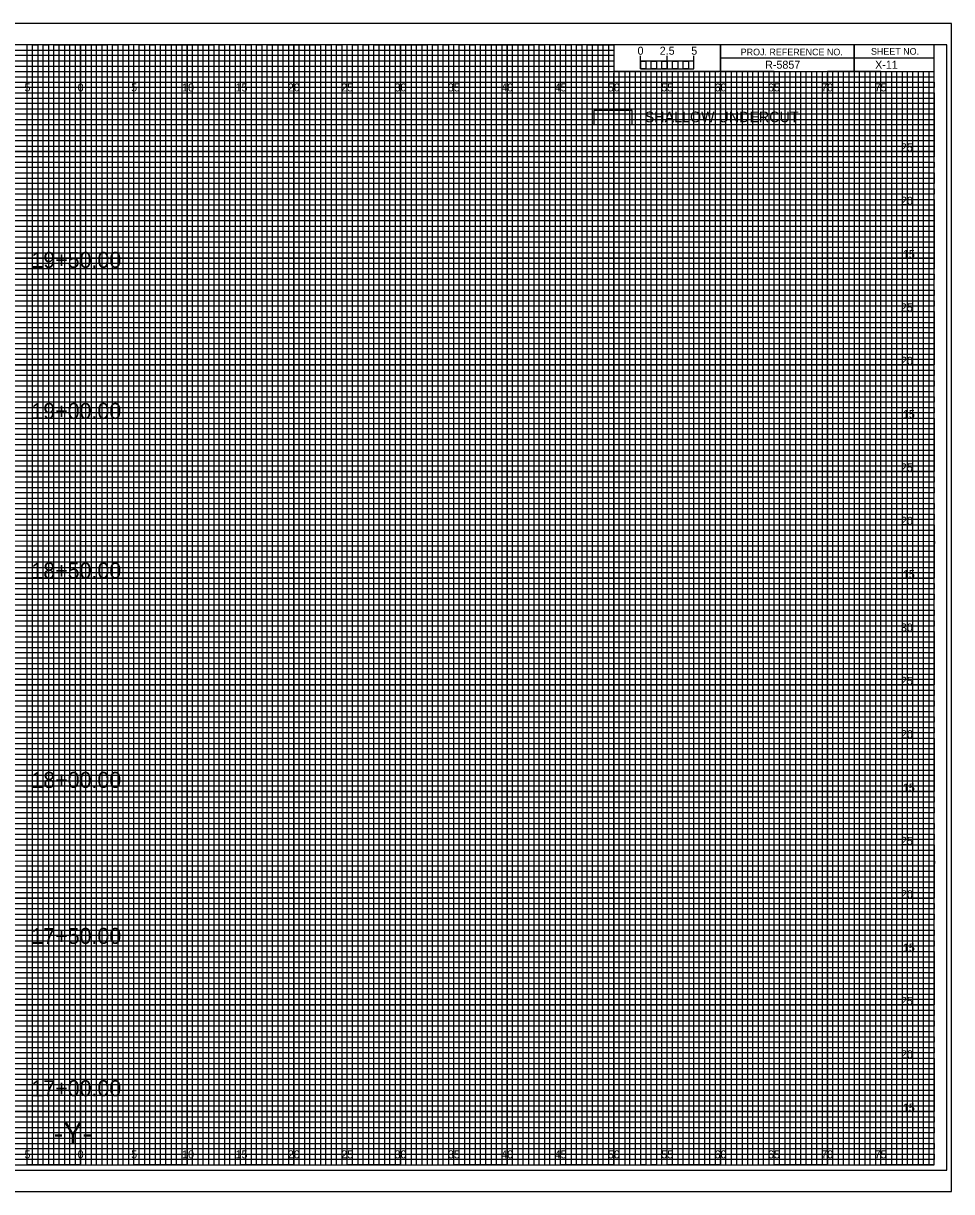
# Model space of a CAD drawing. Extents: x -7 to 162, y -3 to 107.
# Drawn here: x 74.6 to 161.7, y -2.5 to 107 of the extents above; entities that cross this region are included whole.
import ezdxf

# ---------------------------------------------------------------- set-up
doc = ezdxf.new("R2010")
doc.units = 0
for name, color, linetype in [('Old_Level_1', 7, 'Continuous'), ('Prop XS Alignment Label', 7, 'Continuous'), ('Prop XS Bar Scale Labels', 7, 'Continuous'), ('Prop XS Earthwork Undercut', 7, 'Continuous'), ('Prop XS Elevation Labels', 7, 'Continuous'), ('Prop XS Offset Labels', 7, 'Continuous'), ('Prop XS Project Number', 7, 'Continuous'), ('Prop XS Sheet Number', 7, 'Continuous'), ('Prop XS Station Labels', 7, 'Continuous'), ('Sheet Cross Section CELL', 7, 'Continuous'), ('Sheet Cross Section Grid Major CELL', 7, 'Continuous'), ('Sheet Cross Section Grid Middle CELL', 7, 'Continuous'), ('Sheet Cross Section Grid Minor 1 CELL', 7, 'Continuous'), ('Sheet Cross Section Grid Minor 2 CELL', 7, 'Continuous'), ('Sheet Cross Section Scale CELL', 7, 'Continuous'), ('Sheet Cutting Line CELL', 7, 'Continuous'), ('Sheet DOT Grid CELL', 7, 'Continuous'), ('Sheet Plot Border Inside CELL', 7, 'Continuous'), ('Sheet Plot Border Outside CELL', 7, 'Continuous')]:
    doc.layers.add(name, color=color, linetype=linetype)

msp = doc.modelspace()

# ---------------------------------------------------------------- linework, layer by layer
at = {"layer": 'Prop XS Earthwork Undercut'}
msp.add_lwpolyline([(128.12, 97.52), (131.7, 97.52), (131.7, 98.83), (128.12, 98.83), (128.12, 97.52)], dxfattribs=at)
at = {"layer": 'Sheet Cross Section CELL'}
for p, q in [((152.5, 105), (152.5, 102.5)), ((152.5, 102.5), (152.5, 105)), ((160, 103.75), (140, 103.75)), ((140, 103.75), (140, 102.5)), ((140, 102.5), (160, 102.5))]:
    msp.add_line(p, q, dxfattribs=at)
for points in [[(160, 105), (0, 105), (0, 0), (160, 0)], [(140, 105), (130, 105), (130, 102.52), (140, 102.52)], [(160, 105), (140, 105), (140, 102.5), (160, 102.5)]]:
    msp.add_lwpolyline(points, close=True, dxfattribs=at)
at = {"layer": 'Sheet Cross Section Grid Major CELL'}
for p, q in [((75, 105), (70, 105)), ((75, 0), (75, 105)), ((85, 105), (80, 105)), ((80, 105), (80, 0)), ((85, 0), (85, 105)), ((95, 105), (90, 105)), ((90, 105), (90, 0)), ((95, 0), (95, 105)), ((105, 105), (100, 105)), ((100, 105), (100, 0)), ((105, 0), (105, 105)), ((115, 105), (110, 105)), ((110, 105), (110, 0)), ((115, 0), (115, 105)), ((125, 105), (120, 105)), ((120, 105), (120, 0)), ((125, 0), (125, 105)), ((130, 105), (130, 0)), ((135, 0), (135, 102.5)), ((145, 102.5), (140, 102.5)), ((140, 102.5), (140, 0)), ((145, 0), (145, 102.5)), ((155, 102.5), (150, 102.5)), ((150, 102.5), (150, 0)), ((155, 0), (155, 102.5)), ((80, 0), (75, 0)), ((90, 0), (85, 0)), ((100, 0), (95, 0)), ((110, 0), (105, 0)), ((120, 0), (115, 0)), ((130, 0), (125, 0)), ((140, 0), (135, 0)), ((150, 0), (145, 0)), ((160, 0), (155, 0)), ((160, 0), (160, 0))]:
    msp.add_line(p, q, dxfattribs=at)
for points in [[(0, 100), (160, 100), (160, 95), (0, 95)], [(0, 90), (160, 90), (160, 85), (0, 85)], [(0, 80), (160, 80), (160, 75), (0, 75)], [(0, 70), (160, 70), (160, 65), (0, 65)], [(0, 60), (160, 60), (160, 55), (0, 55)], [(0, 50), (160, 50), (160, 45), (0, 45)], [(0, 40), (160, 40), (160, 35), (0, 35)], [(0, 30), (160, 30), (160, 25), (0, 25)], [(0, 20), (160, 20), (160, 15), (0, 15)], [(0, 10), (160, 10), (160, 5), (0, 5)]]:
    msp.add_lwpolyline(points, dxfattribs=at)
at = {"layer": 'Sheet Cross Section Grid Middle CELL'}
for points in [[(72.5, 0), (77.5, 0), (77.5, 105), (82.5, 105), (82.5, 0), (87.5, 0), (87.5, 105), (92.5, 105), (92.5, 0), (97.5, 0), (97.5, 105), (102.5, 105), (102.5, 0), (107.5, 0), (107.5, 105), (112.5, 105), (112.5, 0), (117.5, 0), (117.5, 105), (122.5, 105), (122.5, 0), (127.5, 0), (127.5, 105), (129.97, 105), (130, 105), (130, 102.5), (132.5, 102.5), (132.5, 0), (137.5, 0), (137.5, 102.5), (142.5, 102.5), (142.5, 0), (147.5, 0), (147.5, 102.5), (152.5, 102.5), (152.5, 0), (157.5, 0), (157.5, 102.5)], [(0, 102.5), (137.5, 102.5)], [(0, 92.5), (160, 92.5), (160, 97.5), (0, 97.5)], [(0, 82.5), (160, 82.5), (160, 87.5), (0, 87.5)], [(0, 72.5), (160, 72.5), (160, 77.5), (0, 77.5)], [(0, 62.5), (160, 62.5), (160, 67.5), (0, 67.5)], [(0, 52.5), (160, 52.5), (160, 57.5), (0, 57.5)], [(0, 42.5), (160, 42.5), (160, 47.5), (0, 47.5)], [(0, 32.5), (160, 32.5), (160, 37.5), (0, 37.5)], [(0, 22.5), (160, 22.5), (160, 27.5), (0, 27.5)], [(0, 12.5), (160, 12.5), (160, 17.5), (0, 17.5)], [(0, 2.5), (160, 2.5), (160, 7.5), (0, 7.5)]]:
    msp.add_lwpolyline(points, dxfattribs=at)
at = {"layer": 'Sheet Cross Section Grid Minor 1 CELL'}
for p, q in [((0, 104.5), (130, 104.5)), ((130, 104.5), (130, 103.99)), ((130, 103.99), (0, 103.99)), ((0, 103.5), (130, 103.5)), ((130, 102.95), (0, 102.95)), ((130, 103.5), (130, 102.95)), ((0, 102), (160, 102))]:
    msp.add_line(p, q, dxfattribs=at)
for points in [[(0, 101.5), (135, 101.5), (160, 101.5), (160, 101), (0, 101)], [(0, 100.5), (160, 100.5), (160, 99.5), (0, 99.5)], [(0, 99), (160, 99), (160, 98.5), (0, 98.49)], [(0, 98), (160, 98), (160, 97), (0, 97)], [(0, 96.5), (160, 96.5), (160, 96), (0, 96)], [(0, 95.5), (160, 95.5), (160, 94.5), (0, 94.5)], [(0, 94), (160, 94), (160, 93.5), (0, 93.5)], [(0, 93), (160, 93), (160, 92), (0, 92)], [(0, 91.5), (160, 91.5), (160, 91), (0, 91)], [(0, 90.5), (160, 90.5), (160, 89.5), (0, 89.5)], [(0, 89), (160, 89), (160, 88.5), (0, 88.5)], [(0, 88), (160, 88), (160, 86.98), (160, 86.5), (160, 86), (0, 86)], [(0, 87), (160, 87), (160, 86.5), (0, 86.5)], [(0, 85.5), (160, 85.5), (160, 84.5), (0, 84.52)], [(0, 84.52), (160, 84.5), (160, 84), (0, 84)], [(0, 83.5), (160, 83.5), (160, 83), (0, 83)], [(0, 82), (160, 82), (160, 81.5), (0, 81.5)], [(0, 81), (160, 81), (160, 80.5), (0, 80.5)], [(-0.04, 79.45), (160, 79.45), (160, 78.94), (-0.04, 78.94)], [(0, 78.5), (160, 78.5), (160, 78), (0, 78)], [(0, 77), (160, 77), (160, 76.5), (0, 76.5)], [(0, 76), (160, 76), (160, 75.5), (0, 75.5)], [(0, 74.5), (160, 74.5), (160, 74), (0, 74)], [(0, 73.5), (160, 73.5), (160, 73), (0, 73)], [(0, 72), (160, 72), (160, 71.5), (0, 71.5)], [(0, 71), (160, 71), (160, 70.5), (0, 70.5)], [(0, 69.5), (160, 69.5), (160, 68.99), (0, 69)], [(0, 68.5), (160, 68.5), (160, 68), (0, 68)], [(0, 67), (160, 67), (160, 66.5), (0, 66.5)], [(0, 66), (160, 66), (160, 65.5), (0, 65.5)], [(0, 64.5), (160, 64.5), (160, 64), (0, 64)], [(0, 63.5), (160, 63.5), (160, 63), (0, 63)], [(0, 62), (160, 62), (160, 61.5), (0, 61.5)], [(0, 61), (160, 61), (160, 60.5), (0, 60.5)], [(0, 59.5), (160, 59.5), (160, 59), (0, 59)], [(0, 58.5), (160.03, 58.45), (160, 58), (0, 58)], [(0, 57), (160, 57), (160, 56.5), (0, 56.5)], [(0, 56), (160, 56), (160, 55.5), (0, 55.5)], [(0, 54.5), (160, 54.5), (160, 54), (0, 54)], [(0, 53.5), (160, 53.5), (160, 53), (0, 53)], [(0, 52), (160, 52), (160, 51.5), (0, 51.5)], [(0, 51), (160, 51), (160, 50.5), (0, 50.5)], [(0, 49.5), (160, 49.5), (160, 49), (0, 49)], [(0, 48.5), (160, 48.5), (160, 48), (0, 48)], [(0, 47), (160, 47), (160, 46.5), (0, 46.5)], [(0, 46), (160, 46), (160, 45.5), (0, 45.5)], [(0, 44.5), (160, 44.5), (160, 44), (0, 44)], [(0, 43.5), (160, 43.5), (160, 43), (0, 43)], [(0, 42), (160, 42), (160, 41.5), (0, 41.5)], [(0, 41), (160, 41), (160, 40.5), (0, 40.5)], [(0, 39.5), (160, 39.5), (160, 38.99), (0, 39)], [(0, 38.5), (160, 38.5), (160, 38), (0, 38)], [(0, 37), (160, 37), (160, 36.5), (0, 36.5)], [(0, 36), (160, 36), (160, 35.5), (0, 35.5)], [(0, 34.5), (160, 34.5), (160, 34), (0, 34)], [(0, 33.5), (160, 33.5), (160, 33), (0, 33)], [(0, 32), (160, 32), (160, 31.5), (0, 31.5)], [(0, 31), (160, 31), (160, 30.5), (0, 30.5)], [(0, 29.5), (160, 29.5), (160, 29), (0, 29)], [(0, 28.5), (160.03, 28.46), (160, 28), (0, 28)], [(0, 27), (160, 27), (160, 26.5), (0, 26.5)], [(0, 26), (160, 26), (160, 25.5), (0, 25.5)], [(0, 24.5), (160, 24.5), (160, 24), (0, 24)], [(0, 23.5), (160, 23.5), (160, 23), (0, 23)], [(0, 22), (160, 22), (160, 21.5), (0, 21.5)], [(0, 21), (160, 21), (160, 20.5), (0, 20.5)], [(0, 19.5), (160, 19.5), (160, 19), (0, 19)], [(0, 18.5), (160, 18.5), (160, 18), (0, 18)], [(0, 17), (160, 17), (160, 16.5), (0, 16.5)], [(0, 16), (160, 16), (160, 15.5), (0, 15.5)], [(0, 14.5), (160, 14.5), (160, 14), (0, 14)], [(0, 13.5), (160, 13.5), (160, 13), (0, 13)], [(0, 12), (160, 12), (160, 11.5), (0, 11.5)], [(0, 11), (160, 11), (160, 10.5), (0, 10.5)], [(0, 9.5), (160, 9.5), (160, 9), (0, 9)], [(0, 8.5), (160, 8.5), (160, 8), (0, 8)], [(0, 7), (160, 7), (160, 6.5), (0, 6.5)], [(0, 6), (160, 6), (160, 5.5), (0, 5.5)], [(0, 4.5), (160, 4.5), (160, 4), (0, 4)], [(0, 3.5), (160, 3.5), (160, 3), (0, 3)], [(0, 2), (160, 2), (160, 1.5), (0, 1.5)], [(0, 1), (160, 1), (160, 0.5), (0, 0.5)]]:
    msp.add_lwpolyline(points, dxfattribs=at)
at = {"layer": 'Sheet Cross Section Grid Minor 2 CELL'}
for p, q in [((133.5, 102.5), (133, 102.5)), ((133, 102.5), (133, 0)), ((133.5, 0), (133.5, 102.5)), ((134.5, 102.5), (134, 102.5)), ((134, 102.5), (134, 0)), ((134.5, 0), (134.5, 102.5)), ((133, 0), (132.5, 0)), ((134, 0), (133.5, 0))]:
    msp.add_line(p, q, dxfattribs=at)
for points in [[(75, 0), (75.5, 0), (75.5, 105), (76, 105), (76, 0)], [(76, 0), (76.5, 0), (76.5, 105), (77, 105), (77, 0)], [(77.5, 0), (78, 0), (78, 105), (78.5, 105), (78.5, 0)], [(78.5, 0), (79, 0), (79, 105), (79.5, 105), (79.5, 0)], [(80, 0), (80.5, 0), (80.5, 105), (81, 105), (81, 0)], [(81, 0), (81.5, 0), (81.5, 105), (82, 105), (82, 0)], [(82.5, 0), (83, 0), (83, 105), (83.5, 105), (83.5, 0)], [(83.5, 0), (84, 0), (84, 105), (84.5, 105), (84.5, 0)], [(85, 0), (85.5, 0), (85.5, 105), (86, 105), (86, 0)], [(86, 0), (86.5, 0), (86.5, 105), (87, 105), (87, 0)], [(87.5, 0), (88, 0), (88, 105), (88.5, 105), (88.5, 0)], [(88.5, 0), (89, 0), (89, 105), (89.5, 105), (89.5, 0)], [(90, 0), (90.5, 0), (90.5, 105), (91, 105), (91, 0)], [(91, 0), (91.5, 0), (91.5, 105), (92, 105), (92, 0)], [(92.5, 0), (93, 0), (93, 105), (93.5, 105), (93.5, 0)], [(93.5, 0), (94, 0), (94, 105), (94.5, 105), (94.5, 0)], [(95, 0), (95.5, 0), (95.5, 105), (96, 105), (96, 0)], [(96, 0), (96.5, 0), (96.5, 105), (97, 105), (97, 0)], [(97.5, 0), (98, 0), (98, 105), (98.5, 105), (98.5, 0)], [(98.5, 0), (99, 0), (99, 105), (99.5, 105), (99.5, 0)], [(100, 0), (100.5, 0), (100.5, 105), (101, 105), (101, 0)], [(101, 0), (101.5, 0), (101.5, 105), (102, 105), (102, 0)], [(102.5, 0), (103, 0), (103, 105), (103.5, 105), (103.5, 0)], [(103.5, 0), (104, 0), (104, 105), (104.5, 105), (104.5, 0)], [(105, 0), (105.5, 0), (105.5, 105), (106, 105), (106, 0)], [(106, 0), (106.5, 0), (106.5, 105), (107, 105), (107, 0)], [(107.5, 0), (108, 0), (108, 105), (108.5, 105), (108.5, 0)], [(108.5, 0), (109, 0), (109, 105), (109.5, 105), (109.5, 0)], [(110, 0), (110.5, 0), (110.5, 105), (111, 105), (111, 0)], [(111, 0), (111.5, 0), (111.5, 105), (112, 105), (112, 0)], [(112.5, 0), (113, 0), (113, 105), (113.5, 105), (113.5, 0)], [(113.5, 0), (114, 0), (114, 105), (114.5, 105), (114.5, 0)], [(115, 0), (115.5, 0), (115.5, 105), (116, 105), (116, 0)], [(116, 0), (116.5, 0), (116.5, 105), (117, 105), (117, 0)], [(117.5, 0), (118, 0), (118, 105), (118.5, 105), (118.5, 0)], [(118.5, 0), (119, 0), (119, 105), (119.5, 105), (119.5, 0)], [(120, 0), (120.5, 0), (120.5, 105), (121, 105), (121, 0)], [(121, 0), (121.5, 0), (121.5, 105), (122, 105), (122, 0)], [(122.5, 0), (123, 0), (123, 105), (123.5, 105), (123.5, 0)], [(123.5, 0), (124, 0), (124, 105), (124.5, 105), (124.5, 0)], [(125, 0), (125.5, 0), (125.5, 105), (126, 105), (126, 0)], [(126, 0), (126.5, 0), (126.5, 105), (127, 105), (127, 0)], [(127.5, 0), (128, 0), (128, 105), (128.5, 105), (128.5, 0)], [(128.5, 0), (129, 0), (129, 105), (129.5, 105), (129.5, 0)], [(130, 0), (130.5, 0), (130.5, 102.5), (131.01, 102.5), (131.01, 0)], [(131, 0), (131.5, 0), (131.5, 102.5), (132, 102.5), (132, 0)], [(135, 0), (135.49, 0), (135.49, 102.5), (136, 102.5), (136, 0)], [(136, 0), (136.5, 0), (136.5, 102.5), (137.03, 102.5), (137.03, 0)], [(137.5, 0), (138, 0), (138, 102.5), (138.5, 102.5), (138.5, 0)], [(138.5, 0), (139, 0), (139, 102.5), (139.5, 102.5), (139.5, 0)], [(140, 0), (140.5, 0), (140.5, 102.5), (141, 102.5), (141, 0)], [(141, 0), (141.5, 0), (141.5, 102.5), (142, 102.5), (142, 0)], [(142.5, 0), (143, 0), (143, 102.5), (143.5, 102.5), (143.5, 0)], [(143.5, 0), (144, 0), (144, 102.5), (144.5, 102.5), (144.5, 0)], [(145, 0), (145.5, 0), (145.5, 102.5), (146, 102.5), (146, 0)], [(146, 0), (146.5, 0), (146.5, 102.5), (147, 102.5), (147, 0)], [(147.5, 0), (148, 0), (148, 102.5), (148.5, 102.5), (148.5, 0)], [(148.5, 0), (149, 0), (149, 102.5), (149.5, 102.5), (149.5, 0)], [(150, 0), (150.5, 0), (150.5, 102.5), (151, 102.5), (151, 0)], [(151, 0), (151.5, 0), (151.5, 102.5), (152, 102.5), (152, 0)], [(152.5, 0), (153, 0), (153, 102.5), (153.5, 102.5), (153.5, 0)], [(153.5, 0), (154, 0), (154, 102.5), (154.5, 102.5), (154.5, 0)], [(155, 0), (155.5, 0), (155.5, 102.5), (156, 102.5), (156, 0)], [(156, 0), (156.5, 0), (156.5, 102.5), (157, 102.5), (157, 0)], [(157.5, 0), (158, 0), (158, 102.5), (158.5, 102.5), (158.5, 0)], [(158.5, 0), (159, 0), (159, 102.5), (159.5, 102.5), (159.5, 0)]]:
    msp.add_lwpolyline(points, dxfattribs=at)
at = {"layer": 'Sheet Cross Section Scale CELL'}
for p, q in [((132.5, 102.75), (132.5, 103.95)), ((132.5, 103.45), (132.5, 103.95)), ((135, 102.75), (135, 103.95)), ((137.5, 102.75), (137.5, 103.95)), ((137.5, 103.45), (137.5, 103.95))]:
    msp.add_line(p, q, dxfattribs=at)
for points in [[(137.5, 103.45), (132.5, 103.45), (132.5, 102.75), (137.5, 102.75)], [(132.5, 103.45), (133, 103.45), (133, 102.75), (132.5, 102.75)], [(133.5, 103.45), (134, 103.45), (134, 102.75), (133.5, 102.75)], [(134.5, 103.45), (135, 103.45), (135, 102.75), (134.5, 102.75)], [(135.5, 103.45), (136, 103.45), (136, 102.75), (135.5, 102.75)], [(136.5, 103.45), (137, 103.45), (137, 102.75), (136.5, 102.75)]]:
    msp.add_lwpolyline(points, close=True, dxfattribs=at)
at = {"layer": 'Sheet Cutting Line CELL'}
for p, q in [((161.65, 107), (-6.7, 107)), ((-6.7, -2.5), (161.65, -2.5))]:
    msp.add_line(p, q, dxfattribs=at)
at = {"layer": 'Sheet DOT Grid CELL'}
for p, q in [((75, 0), (75, 105)), ((80, 0), (80, 105)), ((85, 0), (85, 105)), ((90, 0), (90, 105)), ((95, 0), (95, 105)), ((100, 0), (100, 105)), ((105, 0), (105, 105)), ((110, 0), (110, 105)), ((115, 0), (115, 105)), ((120, 0), (120, 105)), ((125, 0), (125, 105)), ((130, 0), (130, 102.34)), ((135, 0), (135, 102.34)), ((140, 0), (140, 102.34)), ((145, 0), (145, 102.34)), ((150, 0), (150, 102.34)), ((155, 0), (155, 102.34)), ((0, 100), (160, 100)), ((0, 95), (160, 95)), ((0, 90), (160, 90)), ((0, 85), (160, 85)), ((0, 80), (160, 80)), ((0, 75), (160, 75)), ((0, 70), (160, 70)), ((0, 65), (160, 65)), ((0, 60), (160, 60)), ((0, 55), (160, 55)), ((0, 50), (160, 50)), ((0, 45), (160, 45)), ((0, 40), (160, 40)), ((0, 35), (160, 35)), ((0, 30), (160, 30)), ((0, 25), (160, 25)), ((0, 20), (160, 20)), ((0, 15), (160, 15)), ((0, 10), (160, 10)), ((0, 5), (160, 5))]:
    msp.add_line(p, q, dxfattribs=at)
at = {"layer": 'Sheet Plot Border Inside CELL'}
msp.add_lwpolyline([(-5.4, -0.5), (161.2, -0.5), (161.2, 105), (-5.4, 105)], close=True, dxfattribs=at)
at = {"layer": 'Sheet Plot Border Outside CELL'}
msp.add_lwpolyline([(-6.7, -2.5), (161.65, -2.5), (161.65, 107), (-6.7, 107)], close=True, dxfattribs=at)

# ---------------------------------------------------------------- texts
at = {"layer": 'Old_Level_1'}
msp.add_text('SHALLOW UNDERCUT', height=1, dxfattribs=at).set_placement((132.89, 97.73))
at = {"layer": 'Prop XS Alignment Label'}
msp.add_text('-Y-', height=2, dxfattribs=at).set_placement((77.5, 2))
at = {"layer": 'Prop XS Bar Scale Labels'}
for s, p in [('2.5', (134.29, 104.06)), ('5', (137.24, 104.06))]:
    msp.add_text(s, height=0.75, dxfattribs=at).set_placement(p)
at = {"layer": 'Prop XS Elevation Labels'}
for s, p in [('25', (156.89, 95)), ('20', (156.9, 90)), ('15', (157.08, 85)), ('25', (156.89, 80)), ('20', (156.9, 75)), ('15', (157.08, 70)), ('25', (156.89, 65)), ('20', (156.9, 60)), ('15', (157.08, 55)), ('30', (156.89, 50)), ('25', (156.89, 45)), ('20', (156.9, 40)), ('15', (157.08, 35)), ('25', (156.89, 30)), ('20', (156.9, 25)), ('15', (157.08, 20)), ('25', (156.89, 15)), ('20', (156.9, 10)), ('15', (157.08, 5))]:
    msp.add_text(s, height=0.75, dxfattribs=at).set_placement(p)
at = {"layer": 'Prop XS Offset Labels'}
for s, p in [('5', (74.74, 100.62)), ('0', (79.73, 100.62)), ('0', (79.73, 100.62)), ('5', (84.74, 100.62)), ('10', (89.52, 100.62)), ('15', (94.53, 100.62)), ('20', (99.43, 100.62)), ('25', (104.44, 100.62)), ('30', (109.43, 100.62)), ('35', (114.44, 100.62)), ('40', (119.43, 100.62)), ('45', (124.44, 100.62)), ('50', (129.43, 100.62)), ('55', (134.44, 100.62)), ('60', (139.43, 100.62)), ('65', (144.44, 100.62)), ('70', (149.43, 100.62)), ('75', (154.44, 100.62)), ('5', (74.74, 0.62)), ('0', (79.73, 0.62)), ('0', (79.73, 0.62)), ('5', (84.74, 0.62)), ('10', (89.52, 0.62)), ('15', (94.53, 0.62)), ('20', (99.43, 0.62)), ('25', (104.44, 0.62)), ('30', (109.43, 0.62)), ('35', (114.44, 0.62)), ('40', (119.43, 0.62)), ('45', (124.44, 0.62)), ('50', (129.43, 0.62)), ('55', (134.44, 0.62)), ('60', (139.43, 0.62)), ('65', (144.44, 0.62)), ('70', (149.43, 0.62)), ('75', (154.44, 0.62))]:
    msp.add_text(s, height=0.75, dxfattribs=at).set_placement(p)
at = {"layer": 'Prop XS Project Number'}
msp.add_text('R-5857', height=0.75, dxfattribs=at).set_placement((144.17, 102.75))
at = {"layer": 'Prop XS Sheet Number'}
msp.add_text('X-11', height=0.75, dxfattribs=at).set_placement((154.48, 102.75))
at = {"layer": 'Prop XS Station Labels'}
for s, p in [('19+50.00', (75.39, 84.08)), ('19+00.00', (75.39, 69.92)), ('18+50.00', (75.39, 54.96)), ('18+00.00', (75.39, 35.34)), ('17+50.00', (75.39, 20.72)), ('17+00.00', (75.39, 6.44))]:
    msp.add_text(s, height=1.5, dxfattribs=at).set_placement(p)
at = {"layer": 'Sheet Cross Section CELL'}
for s, p in [('PROJ. REFERENCE NO.', (141.88, 104)), ('SHEET NO.', (154.09, 104.06))]:
    msp.add_text(s, height=0.625, dxfattribs=at).set_placement(p)
at = {"layer": 'Sheet Cross Section Scale CELL'}
msp.add_text('0', height=0.75, dxfattribs=at).set_placement((132.21, 104.06))

doc.saveas('drawing.dxf')
